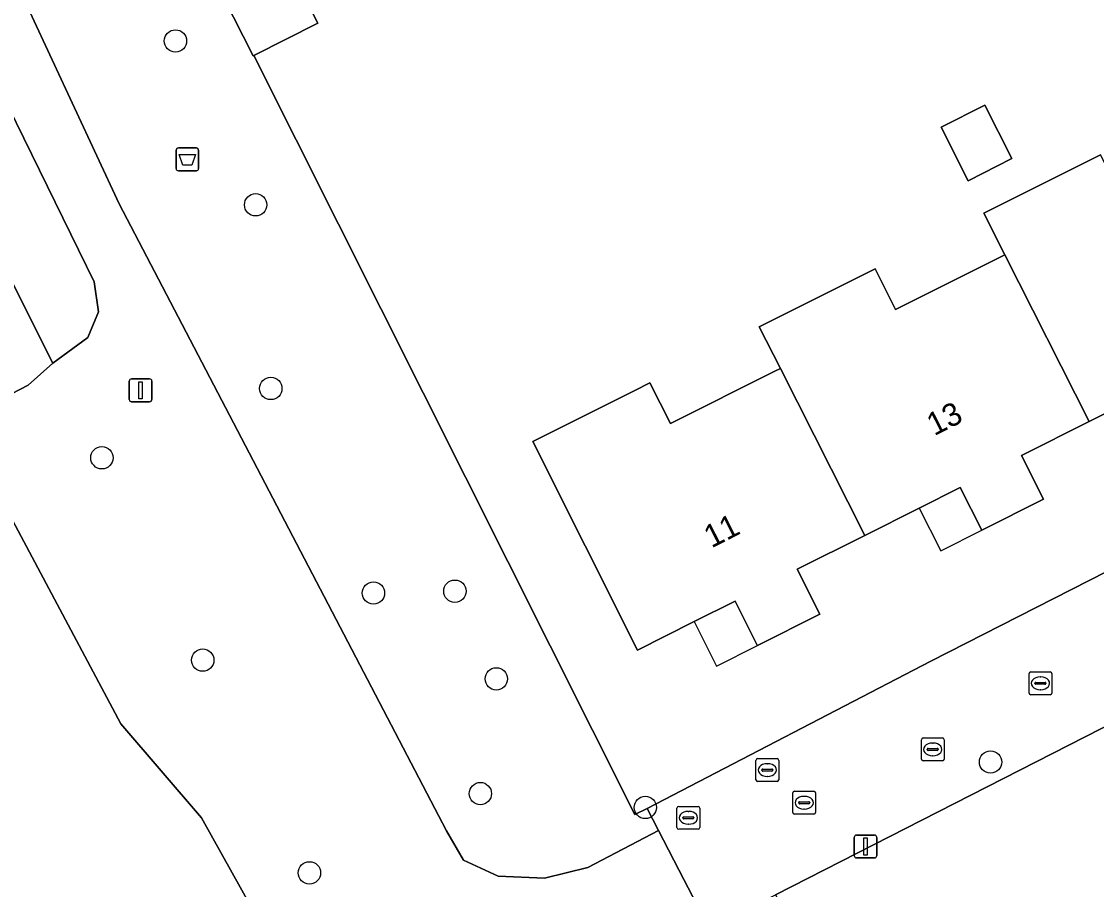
# Model space of a CAD drawing. Extents: x 162722 to 165104, y 384719 to 386284.
# Drawn here: x 163805.66 to 163852.76, y 385001.53 to 385039.57 of the extents above; entities that cross this region are included whole.
import ezdxf

# ---------------------------------------------------------------- set-up
doc = ezdxf.new("R2010")
doc.units = 0
for name, color, linetype in [('IMGEO_Afvalbak', 7, 'Continuous'), ('IMGEO_Boom', 7, 'Continuous'), ('IMGEO_Brandkraan', 7, 'Continuous'), ('IMGEO_Erf', 7, 'Continuous'), ('IMGEO_Groenvoorziening', 7, 'Continuous'), ('IMGEO_Kolk', 7, 'Continuous'), ('IMGEO_Lichtmast', 7, 'Continuous'), ('IMGEO_Pand', 7, 'Continuous'), ('IMGEO_Pand_nummerreeks', 7, 'Continuous'), ('IMGEO_Pand_overbouw', 7, 'Continuous'), ('IMGEO_Parkeervlak_open', 7, 'Continuous'), ('IMGEO_Rioolput', 7, 'Continuous')]:
    doc.layers.add(name, color=color, linetype=linetype)

msp = doc.modelspace()

# ---------------------------------------------------------------- linework, layer by layer
at = {"layer": 'IMGEO_Afvalbak'}
for p, q in [((163812.531, 385034.023), (163813.321, 385034.023)), ((163813.321, 385034.023), (163812.531, 385034.023)), ((163812.431, 385033.123), (163812.431, 385033.923)), ((163812.431, 385033.923), (163812.431, 385033.123)), ((163813.421, 385033.923), (163813.421, 385033.123)), ((163813.421, 385033.123), (163813.421, 385033.923)), ((163813.321, 385033.023), (163812.531, 385033.023)), ((163812.531, 385033.023), (163813.321, 385033.023))]:
    msp.add_line(p, q, dxfattribs=at)
msp.add_lwpolyline([(163812.574, 385033.737), (163813.278, 385033.737), (163813.129, 385033.267), (163812.723, 385033.267), (163812.574, 385033.737)], dxfattribs=at)
for centre, start, end in [((163812.531, 385033.923), 90, 180), ((163812.531, 385033.923), 90, 180), ((163813.321, 385033.923), 0, 90), ((163813.321, 385033.923), 360, 90), ((163812.531, 385033.123), 180, 270), ((163812.531, 385033.123), 180, 270), ((163813.321, 385033.123), 270, 0), ((163813.321, 385033.123), 270, 0)]:
    msp.add_arc(centre, 0.1, start, end, dxfattribs=at)
at = {"layer": 'IMGEO_Boom'}
for centre in [(163812.405, 385038.713), (163815.917, 385031.534), (163816.582, 385023.484), (163809.182, 385020.449), (163824.649, 385014.601), (163821.081, 385014.522), (163813.6, 385011.58), (163826.463, 385010.761), (163848.117, 385007.116), (163825.766, 385005.733), (163832.992, 385005.127), (163818.275, 385002.259)]:
    msp.add_circle(centre, 0.489, dxfattribs=at)
at = {"layer": 'IMGEO_Brandkraan'}
for p, q in [((163837.839, 385006.338), (163837.839, 385007.19)), ((163837.914, 385007.264), (163838.766, 385007.264)), ((163838.84, 385007.19), (163838.84, 385006.338)), ((163838.098, 385006.758), (163838.098, 385006.77)), ((163838.536, 385006.721), (163838.138, 385006.721)), ((163838.141, 385006.807), (163838.539, 385006.807)), ((163838.327, 385007.044), (163838.352, 385007.044)), ((163838.582, 385006.77), (163838.582, 385006.758)), ((163838.766, 385006.264), (163837.914, 385006.264)), ((163838.35, 385006.484), (163838.325, 385006.484))]:
    msp.add_line(p, q, dxfattribs=at)
for points in [[(163837.839, 385006.338), (163837.839, 385007.19)], [(163837.914, 385007.264), (163838.766, 385007.264)], [(163838.84, 385007.19), (163838.84, 385006.338)], [(163838.766, 385006.264), (163837.914, 385006.264)]]:
    msp.add_lwpolyline(points, dxfattribs=at)
for centre, radius, start, end in [((163837.916, 385007.188), 0.0765, 91.552, 178.448), ((163837.916, 385007.188), 0.0765, 91.552, 178.448), ((163838.764, 385007.188), 0.0765, 1.552, 88.448), ((163838.764, 385007.188), 0.0765, 1.552, 88.448), ((163838.138, 385006.767), 0.0403, 85.8775, 175.7526), ((163838.135, 385006.757), 0.0366, 178.938, 274.7102), ((163838.539, 385006.764), 0.043, 264.8664, 352.4533), ((163838.543, 385006.769), 0.0386, 1.7309, 96.639), ((163837.916, 385006.34), 0.0765, 181.552, 268.448), ((163837.916, 385006.34), 0.0765, 181.552, 268.448), ((163838.764, 385006.34), 0.0765, 271.552, 358.448), ((163838.764, 385006.34), 0.0765, 271.552, 358.448)]:
    msp.add_arc(centre, radius, start, end, dxfattribs=at)
for centre, major_axis, ratio, start_param, end_param in [((163838.326, 385006.764), (-0.387, 0.002), 0.722429, 4.712389, 7.853982), ((163838.351, 385006.764), (-0.39, 0.002), 0.717154, 1.570796, 4.712389)]:
    msp.add_ellipse(centre, major_axis=major_axis, ratio=ratio, start_param=start_param, end_param=end_param, dxfattribs=at)
at = {"layer": 'IMGEO_Erf'}
for points in [[(163857.691, 385060.711), (163852.747, 385058.247), (163847.83, 385055.75), (163838, 385050.758), (163837.08, 385052.574), (163836.867, 385052.466), (163832.345, 385050.169), (163833.255, 385048.378), (163829.454, 385046.447), (163830.58, 385044.228), (163829.297, 385043.578), (163824.531, 385041.162), (163823.391, 385043.412), (163822.494, 385042.957), (163818.036, 385040.692), (163818.642, 385039.498), (163815.835, 385038.073), (163832.532, 385004.815), (163833.069, 385005.08), (163845.497, 385011.535), (163866.282, 385022.121)], [(163854.782, 385023.211), (163852.445, 385022.04), (163849.48, 385020.553), (163850.442, 385018.633), (163847.731, 385017.274), (163846.792, 385019.146), (163844.995, 385018.245), (163842.607, 385017.048), (163839.649, 385015.565), (163840.639, 385013.589), (163837.901, 385012.216), (163837.887, 385012.244), (163836.924, 385014.166), (163835.136, 385013.27), (163832.643, 385012.021), (163828.061, 385021.161), (163832.531, 385023.402), (163833.194, 385023.734), (163834.091, 385021.945), (163838.667, 385024.239), (163838.91, 385024.361), (163837.986, 385026.188), (163843.059, 385028.731), (163843.955, 385026.943), (163848.451, 385029.197), (163848.75, 385029.347), (163847.83, 385031.167), (163852.942, 385033.729)], [(163883.755, 384994.016), (163880.721, 385000), (163880.397, 385000.638), (163874.468, 385012.289), (163872.821, 385015.517), (163871.523, 385018.049), (163838.691, 385001.291), (163859.479, 384960.25), (163871.364, 384937.05), (163900.699, 384951.83)]]:
    msp.add_lwpolyline(points, dxfattribs=at)
msp.add_lwpolyline([(163847.869, 385035.905), (163849.056, 385033.556), (163847.137, 385032.586), (163845.95, 385034.934)], close=True, dxfattribs=at)
at = {"layer": 'IMGEO_Groenvoorziening'}
for points in [[(163776.799, 385086.81), (163778.131, 385085.393), (163779.162, 385082.093), (163791.359, 385057.157), (163791.535, 385054.401), (163792.881, 385051.428), (163794.209, 385050.139), (163807.026, 385024.596), (163808.566, 385025.713), (163809.035, 385026.84), (163808.847, 385028.154), (163805.421, 385035.138), (163798.727, 385048.566), (163793.575, 385058.788), (163790.143, 385065.128), (163788.181, 385067.57), (163786.027, 385073.647), (163785.482, 385074.719), (163784.543, 385076.561), (163782.934, 385079.72), (163780.143, 385084.723), (163778.682, 385086.223), (163777.874, 385086.761)], [(163815.835, 385038.073), (163815.81, 385038.06), (163811.049, 385047.435), (163810.595, 385048.328), (163810.667, 385048.365), (163807.878, 385053.92), (163808.904, 385054.472), (163807.854, 385056.531), (163807.737, 385056.76), (163805.936, 385055.672), (163804.901, 385054.618), (163803.731, 385053.009), (163802.886, 385051.473), (163802.735, 385048.896), (163804.058, 385044.204), (163809.943, 385031.579), (163824.283, 385004.106), (163825.024, 385002.809), (163826.54, 385002.113), (163828.577, 385002.032), (163830.475, 385002.5), (163833.567, 385004.119), (163833.069, 385005.08), (163832.532, 385004.815)]]:
    msp.add_lwpolyline(points, close=True, dxfattribs=at)
for points in [[(163783.871, 385053.812), (163791.526, 385039.145), (163795.181, 385031.929), (163797.817, 385026.586), (163796.607, 385025.906), (163799.345, 385020.634), (163799.657, 385020.033), (163804.115, 385022.684), (163805.95, 385023.625), (163807.026, 385024.596), (163794.209, 385050.139)], [(163798.727, 385048.566), (163805.421, 385035.138), (163808.847, 385028.154), (163809.035, 385026.84), (163808.566, 385025.713), (163807.026, 385024.596), (163805.95, 385023.625), (163804.115, 385022.684), (163799.657, 385020.033), (163800.305, 385018.786), (163803.653, 385020.249), (163804.532, 385019.055), (163810.006, 385008.789), (163813.545, 385004.677), (163817.003, 384998.463), (163818.75, 384994.205), (163821.467, 384989.96), (163821.501, 384989.907), (163826.306, 384989.862), (163827.686, 384987.569), (163834.379, 384974.661), (163840.9, 384963.114), (163856.826, 384929.784)], [(163835.644, 385000.113), (163834.679, 385001.975), (163833.567, 385004.119), (163830.475, 385002.5), (163828.577, 385002.032), (163826.54, 385002.113), (163825.024, 385002.809), (163824.283, 385004.106), (163809.943, 385031.579), (163804.058, 385044.204)], [(163850.721, 384926.692), (163848.58, 384930.349), (163846.709, 384935.032), (163844.556, 384940.861), (163842.832, 384945.951), (163840.819, 384951.291), (163838.385, 384956.066), (163834.732, 384959.963), (163833.717, 384961.939), (163831.854, 384966.281), (163829.673, 384970.329), (163827.544, 384974.063), (163828.596, 384975.798), (163825.844, 384980.889), (163823.674, 384985.023), (163822.453, 384988.419), (163821.501, 384989.907), (163821.467, 384989.96), (163818.75, 384994.205), (163817.003, 384998.463), (163813.545, 385004.677), (163810.006, 385008.789), (163804.532, 385019.055)]]:
    msp.add_lwpolyline(points, dxfattribs=at)
at = {"layer": 'IMGEO_Kolk'}
for p, q in [((163849.805, 385010.138), (163849.805, 385010.99)), ((163849.88, 385011.064), (163850.732, 385011.064)), ((163850.806, 385010.99), (163850.806, 385010.138)), ((163850.064, 385010.558), (163850.064, 385010.57)), ((163850.502, 385010.521), (163850.104, 385010.521)), ((163850.107, 385010.607), (163850.505, 385010.607)), ((163850.293, 385010.844), (163850.318, 385010.844)), ((163850.548, 385010.57), (163850.548, 385010.558)), ((163850.732, 385010.064), (163849.88, 385010.064)), ((163850.316, 385010.284), (163850.291, 385010.284)), ((163839.453, 385004.907), (163839.453, 385005.759)), ((163839.528, 385005.833), (163840.38, 385005.833)), ((163840.454, 385005.759), (163840.454, 385004.907)), ((163839.712, 385005.327), (163839.712, 385005.339)), ((163840.15, 385005.29), (163839.752, 385005.29)), ((163839.755, 385005.376), (163840.153, 385005.376)), ((163839.941, 385005.613), (163839.966, 385005.613)), ((163840.196, 385005.339), (163840.196, 385005.327)), ((163840.38, 385004.833), (163839.528, 385004.833)), ((163839.964, 385005.053), (163839.939, 385005.053))]:
    msp.add_line(p, q, dxfattribs=at)
for points in [[(163849.805, 385010.138), (163849.805, 385010.99)], [(163849.88, 385011.064), (163850.732, 385011.064)], [(163850.806, 385010.99), (163850.806, 385010.138)], [(163850.732, 385010.064), (163849.88, 385010.064)], [(163839.453, 385004.907), (163839.453, 385005.759)], [(163839.528, 385005.833), (163840.38, 385005.833)], [(163840.454, 385005.759), (163840.454, 385004.907)], [(163840.38, 385004.833), (163839.528, 385004.833)]]:
    msp.add_lwpolyline(points, dxfattribs=at)
for centre, radius, start, end in [((163849.882, 385010.988), 0.0765, 91.552, 178.448), ((163849.882, 385010.988), 0.0765, 91.552, 178.448), ((163850.73, 385010.988), 0.0765, 1.552, 88.448), ((163850.73, 385010.988), 0.0765, 1.552, 88.448), ((163850.104, 385010.567), 0.0403, 85.8775, 175.7526), ((163850.101, 385010.557), 0.0366, 178.938, 274.7102), ((163850.505, 385010.564), 0.043, 264.8664, 352.4533), ((163850.509, 385010.569), 0.0386, 1.7309, 96.639), ((163849.882, 385010.14), 0.0765, 181.552, 268.448), ((163849.882, 385010.14), 0.0765, 181.552, 268.448), ((163850.73, 385010.14), 0.0765, 271.552, 358.448), ((163850.73, 385010.14), 0.0765, 271.552, 358.448), ((163839.53, 385005.757), 0.0765, 91.552, 178.448), ((163839.53, 385005.757), 0.0765, 91.552, 178.448), ((163840.378, 385005.757), 0.0765, 1.552, 88.448), ((163840.378, 385005.757), 0.0765, 1.552, 88.448), ((163839.752, 385005.336), 0.0403, 85.8775, 175.7526), ((163839.749, 385005.326), 0.0366, 178.938, 274.7102), ((163840.153, 385005.333), 0.043, 264.8664, 352.4533), ((163840.157, 385005.338), 0.0386, 1.7309, 96.639), ((163839.53, 385004.909), 0.0765, 181.552, 268.448), ((163839.53, 385004.909), 0.0765, 181.552, 268.448), ((163840.378, 385004.909), 0.0765, 271.552, 358.448), ((163840.378, 385004.909), 0.0765, 271.552, 358.448)]:
    msp.add_arc(centre, radius, start, end, dxfattribs=at)
for centre, major_axis, ratio, start_param, end_param in [((163850.292, 385010.564), (-0.387, 0.002), 0.722429, 4.712389, 7.853982), ((163850.317, 385010.564), (-0.39, 0.002), 0.717154, 1.570796, 4.712389), ((163839.94, 385005.333), (-0.387, 0.002), 0.722429, 4.712389, 7.853982), ((163839.965, 385005.333), (-0.39, 0.002), 0.717154, 1.570796, 4.712389)]:
    msp.add_ellipse(centre, major_axis=major_axis, ratio=ratio, start_param=start_param, end_param=end_param, dxfattribs=at)
at = {"layer": 'IMGEO_Lichtmast'}
for p, q in [((163810.383, 385023.005), (163810.383, 385023.805)), ((163810.383, 385023.805), (163810.383, 385023.005)), ((163810.483, 385023.905), (163811.273, 385023.905)), ((163811.273, 385023.905), (163810.483, 385023.905)), ((163811.373, 385023.805), (163811.373, 385023.005)), ((163811.373, 385023.005), (163811.373, 385023.805)), ((163811.273, 385022.905), (163810.483, 385022.905)), ((163810.483, 385022.905), (163811.273, 385022.905)), ((163842.146, 385003.014), (163842.146, 385003.814)), ((163842.146, 385003.814), (163842.146, 385003.014)), ((163842.246, 385003.914), (163843.036, 385003.914)), ((163843.036, 385003.914), (163842.246, 385003.914)), ((163843.136, 385003.814), (163843.136, 385003.014)), ((163843.136, 385003.014), (163843.136, 385003.814)), ((163843.036, 385002.914), (163842.246, 385002.914)), ((163842.246, 385002.914), (163843.036, 385002.914))]:
    msp.add_line(p, q, dxfattribs=at)
for points in [[(163810.803, 385023.78), (163810.953, 385023.78), (163810.953, 385023.03), (163810.803, 385023.03), (163810.803, 385023.78)], [(163842.566, 385003.789), (163842.716, 385003.789), (163842.716, 385003.039), (163842.566, 385003.039), (163842.566, 385003.789)]]:
    msp.add_lwpolyline(points, dxfattribs=at)
for centre, start, end in [((163810.483, 385023.805), 90, 180), ((163810.483, 385023.805), 90, 180), ((163811.273, 385023.805), 0, 90), ((163811.273, 385023.805), 360, 90), ((163810.483, 385023.005), 180, 270), ((163810.483, 385023.005), 180, 270), ((163811.273, 385023.005), 270, 0), ((163811.273, 385023.005), 270, 0), ((163842.246, 385003.814), 90, 180), ((163842.246, 385003.814), 90, 180), ((163843.036, 385003.814), 0, 90), ((163843.036, 385003.814), 360, 90), ((163842.246, 385003.014), 180, 270), ((163842.246, 385003.014), 180, 270), ((163843.036, 385003.014), 270, 0), ((163843.036, 385003.014), 270, 0)]:
    msp.add_arc(centre, 0.1, start, end, dxfattribs=at)
at = {"layer": 'IMGEO_Pand'}
for points in [[(163813.428, 385049.766), (163810.667, 385048.365), (163810.595, 385048.328), (163811.049, 385047.435), (163815.81, 385038.06), (163815.835, 385038.073), (163818.642, 385039.498), (163818.036, 385040.692)], [(163845.95, 385034.934), (163847.137, 385032.586), (163849.056, 385033.556), (163847.869, 385035.905)], [(163858.526, 385034.223), (163858.334, 385034.127), (163853.865, 385031.887), (163852.942, 385033.729), (163847.83, 385031.167), (163848.75, 385029.347), (163852.445, 385022.04), (163854.782, 385023.211), (163856.572, 385024.108), (163857.504, 385022.214), (163860.371, 385023.653), (163859.44, 385025.51), (163862.226, 385026.907)], [(163848.75, 385029.347), (163848.451, 385029.197), (163843.955, 385026.943), (163843.059, 385028.731), (163837.986, 385026.188), (163838.91, 385024.361), (163842.607, 385017.048), (163844.995, 385018.245), (163846.792, 385019.146), (163847.731, 385017.274), (163850.442, 385018.633), (163849.48, 385020.553), (163852.445, 385022.04)], [(163838.91, 385024.361), (163838.667, 385024.239), (163834.091, 385021.945), (163833.194, 385023.734), (163832.531, 385023.402), (163828.061, 385021.161), (163832.643, 385012.021), (163835.136, 385013.27), (163836.924, 385014.166), (163837.887, 385012.244), (163837.901, 385012.216), (163840.639, 385013.589), (163839.649, 385015.565), (163842.607, 385017.048)]]:
    msp.add_lwpolyline(points, close=True, dxfattribs=at)
at = {"layer": 'IMGEO_Pand_overbouw'}
for points in [[(163846.792, 385019.146), (163844.995, 385018.245), (163845.934, 385016.373), (163847.731, 385017.274)], [(163836.924, 385014.166), (163835.136, 385013.27), (163836.113, 385011.32), (163837.901, 385012.216)]]:
    msp.add_lwpolyline(points, close=True, dxfattribs=at)
at = {"layer": 'IMGEO_Parkeervlak_open'}
msp.add_lwpolyline([(163871.523, 385018.049), (163870.157, 385020.662), (163876.358, 385023.81), (163878.883, 385025.088), (163886.115, 385028.743), (163884.686, 385031.448), (163866.282, 385022.121), (163845.497, 385011.535), (163833.069, 385005.08), (163833.567, 385004.119), (163834.679, 385001.975), (163835.644, 385000.113), (163835.703, 385000), (163835.779, 384999.853), (163836.088, 385000), (163838.691, 385001.291)], close=True, dxfattribs=at)
at = {"layer": 'IMGEO_Rioolput'}
for p, q in [((163845.086, 385007.243), (163845.086, 385008.095)), ((163845.161, 385008.169), (163846.013, 385008.169)), ((163846.087, 385008.095), (163846.087, 385007.243)), ((163845.345, 385007.663), (163845.345, 385007.675)), ((163845.783, 385007.626), (163845.385, 385007.626)), ((163845.388, 385007.712), (163845.786, 385007.712)), ((163845.574, 385007.949), (163845.599, 385007.949)), ((163845.829, 385007.675), (163845.829, 385007.663)), ((163846.013, 385007.169), (163845.161, 385007.169)), ((163845.597, 385007.389), (163845.572, 385007.389)), ((163834.379, 385004.247), (163834.379, 385005.099)), ((163834.454, 385005.173), (163835.306, 385005.173)), ((163834.867, 385004.953), (163834.892, 385004.953)), ((163835.38, 385005.099), (163835.38, 385004.247)), ((163834.638, 385004.667), (163834.638, 385004.679)), ((163835.076, 385004.63), (163834.678, 385004.63)), ((163834.681, 385004.716), (163835.079, 385004.716)), ((163834.89, 385004.393), (163834.865, 385004.393)), ((163835.122, 385004.679), (163835.122, 385004.667)), ((163835.306, 385004.173), (163834.454, 385004.173))]:
    msp.add_line(p, q, dxfattribs=at)
for points in [[(163845.086, 385007.243), (163845.086, 385008.095)], [(163845.161, 385008.169), (163846.013, 385008.169)], [(163846.087, 385008.095), (163846.087, 385007.243)], [(163846.013, 385007.169), (163845.161, 385007.169)], [(163834.379, 385004.247), (163834.379, 385005.099)], [(163834.454, 385005.173), (163835.306, 385005.173)], [(163835.38, 385005.099), (163835.38, 385004.247)], [(163835.306, 385004.173), (163834.454, 385004.173)]]:
    msp.add_lwpolyline(points, dxfattribs=at)
for centre, radius, start, end in [((163845.163, 385008.093), 0.0765, 91.552, 178.448), ((163845.163, 385008.093), 0.0765, 91.552, 178.448), ((163846.011, 385008.093), 0.0765, 1.552, 88.448), ((163846.011, 385008.093), 0.0765, 1.552, 88.448), ((163845.385, 385007.672), 0.0403, 85.8775, 175.7526), ((163845.382, 385007.662), 0.0366, 178.938, 274.7102), ((163845.786, 385007.669), 0.043, 264.8664, 352.4533), ((163845.79, 385007.674), 0.0386, 1.7309, 96.639), ((163845.163, 385007.245), 0.0765, 181.552, 268.448), ((163845.163, 385007.245), 0.0765, 181.552, 268.448), ((163846.011, 385007.245), 0.0765, 271.552, 358.448), ((163846.011, 385007.245), 0.0765, 271.552, 358.448), ((163834.456, 385005.097), 0.0765, 91.552, 178.448), ((163834.456, 385005.097), 0.0765, 91.552, 178.448), ((163835.304, 385005.097), 0.0765, 1.552, 88.448), ((163835.304, 385005.097), 0.0765, 1.552, 88.448), ((163834.678, 385004.676), 0.0403, 85.8775, 175.7526), ((163834.675, 385004.666), 0.0366, 178.938, 274.7102), ((163835.079, 385004.673), 0.043, 264.8664, 352.4533), ((163835.083, 385004.678), 0.0386, 1.7309, 96.639), ((163834.456, 385004.249), 0.0765, 181.552, 268.448), ((163834.456, 385004.249), 0.0765, 181.552, 268.448), ((163835.304, 385004.249), 0.0765, 271.552, 358.448), ((163835.304, 385004.249), 0.0765, 271.552, 358.448)]:
    msp.add_arc(centre, radius, start, end, dxfattribs=at)
for centre, major_axis, ratio, start_param, end_param in [((163845.573, 385007.669), (-0.387, 0.002), 0.722429, 4.712389, 7.853982), ((163845.598, 385007.669), (-0.39, 0.002), 0.717154, 1.570796, 4.712389), ((163834.866, 385004.673), (-0.387, 0.002), 0.722429, 4.712389, 7.853982), ((163834.891, 385004.673), (-0.39, 0.002), 0.717154, 1.570796, 4.712389)]:
    msp.add_ellipse(centre, major_axis=major_axis, ratio=ratio, start_param=start_param, end_param=end_param, dxfattribs=at)

# ---------------------------------------------------------------- texts
at = {"layer": 'IMGEO_Pand_nummerreeks'}
for s, p in [('13', (163845.649, 385021.39)), ('11', (163835.888, 385016.475))]:
    msp.add_text(s, height=1, rotation=26.7228, dxfattribs=at).set_placement(p)

doc.saveas('drawing.dxf')
